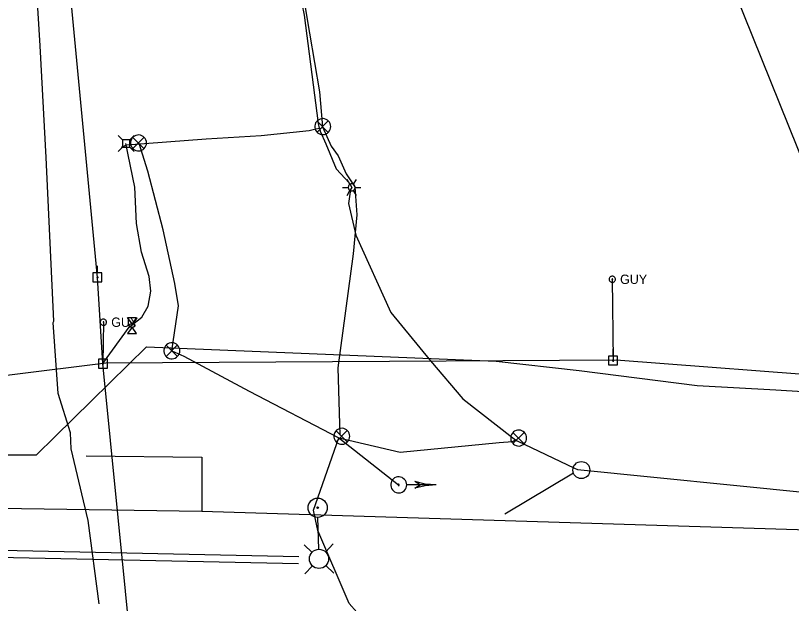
# Model space of a CAD drawing. Extents: x 596028 to 606371, y 330010 to 403088.
# Drawn here: x 603449.9 to 603769.8, y 349952.6 to 350195 of the extents above; entities that cross this region are included whole.
import ezdxf

# ---------------------------------------------------------------- set-up
doc = ezdxf.new("R2010")
doc.units = 0
for name, color, linetype in [('E_FTMS', 7, 'Continuous'), ('E_FTMS_Conduit', 7, 'Continuous'), ('E_LTG', 7, 'Continuous'), ('E_LTG_CID', 7, 'Continuous'), ('E_UTL_E', 7, 'Continuous'), ('E_UTL_E_Bold', 7, 'Continuous'), ('E_UTL_E_UG', 7, 'Continuous'), ('E_UTL_EGuyWire', 7, 'Continuous'), ('E_UTL_EPowerPole', 7, 'Continuous'), ('E_UTL_FO_UG_QWEST', 7, 'Continuous'), ('E_UTL_G_UG', 7, 'Continuous'), ('E_UTL_Overhead', 7, 'Continuous'), ('E_UTL_T_UG', 7, 'Continuous')]:
    doc.layers.add(name, color=color, linetype=linetype)

msp = doc.modelspace()

# ---------------------------------------------------------------- linework, layer by layer
at = {"layer": 'E_FTMS'}
msp.add_line((603679.91, 350006.37), (603651.7, 349989.5), dxfattribs=at)
for points in [[(603579.86, 350149.18), (603579.8, 350149.8), (603579.63, 350150.41), (603579.34, 350150.96), (603578.95, 350151.46), (603578.48, 350151.87), (603577.93, 350152.18), (603577.34, 350152.39), (603576.72, 350152.48), (603576.09, 350152.45), (603575.48, 350152.3), (603574.91, 350152.04), (603574.4, 350151.67), (603573.97, 350151.22), (603573.63, 350150.69), (603573.4, 350150.11), (603573.28, 350149.49), (603573.28, 350148.87), (603573.4, 350148.25), (603573.63, 350147.67), (603573.97, 350147.14), (603574.4, 350146.69), (603574.91, 350146.32), (603575.48, 350146.06), (603576.09, 350145.91), (603576.72, 350145.88), (603577.34, 350145.97), (603577.93, 350146.18), (603578.48, 350146.49), (603578.95, 350146.9), (603579.34, 350147.4), (603579.63, 350147.95), (603579.8, 350148.55), (603579.86, 350149.18)], [(603578.83, 350151.51), (603574.22, 350146.86)], [(603574.22, 350151.47), (603578.87, 350146.81)], [(603503.94, 350142.46), (603503.88, 350143.08), (603503.71, 350143.68), (603503.42, 350144.24), (603503.03, 350144.74), (603502.56, 350145.15), (603502.01, 350145.46), (603501.42, 350145.66), (603500.8, 350145.75), (603500.17, 350145.72), (603499.56, 350145.58), (603498.99, 350145.32), (603498.48, 350144.95), (603498.05, 350144.5), (603497.71, 350143.97), (603497.48, 350143.39), (603497.36, 350142.77), (603497.36, 350142.14), (603497.48, 350141.53), (603497.71, 350140.95), (603498.05, 350140.42), (603498.48, 350139.96), (603498.99, 350139.6), (603499.56, 350139.34), (603500.17, 350139.19), (603500.8, 350139.16), (603501.42, 350139.25), (603502.01, 350139.46), (603502.56, 350139.77), (603503.03, 350140.18), (603503.42, 350140.67), (603503.71, 350141.23), (603503.88, 350141.83), (603503.94, 350142.46)], [(603502.91, 350144.79), (603498.3, 350140.14)], [(603498.3, 350144.74), (603502.95, 350140.09)], [(603517.67, 350056.79), (603517.61, 350057.41), (603517.43, 350058.01), (603517.15, 350058.57), (603516.76, 350059.07), (603516.28, 350059.48), (603515.74, 350059.79), (603515.15, 350060), (603514.53, 350060.08), (603513.9, 350060.05), (603513.29, 350059.91), (603512.72, 350059.65), (603512.21, 350059.28), (603511.78, 350058.83), (603511.44, 350058.3), (603511.2, 350057.72), (603511.09, 350057.1), (603511.09, 350056.47), (603511.2, 350055.86), (603511.44, 350055.28), (603511.78, 350054.75), (603512.21, 350054.29), (603512.72, 350053.93), (603513.29, 350053.67), (603513.9, 350053.52), (603514.53, 350053.49), (603515.15, 350053.58), (603515.74, 350053.79), (603516.28, 350054.1), (603516.76, 350054.51), (603517.15, 350055), (603517.43, 350055.56), (603517.61, 350056.16), (603517.67, 350056.79)], [(603516.63, 350059.12), (603512.02, 350054.47)], [(603512.02, 350059.08), (603516.68, 350054.42)], [(603587.73, 350021.54), (603587.67, 350022.16), (603587.49, 350022.76), (603587.2, 350023.32), (603586.82, 350023.81), (603586.34, 350024.23), (603585.8, 350024.54), (603585.21, 350024.74), (603584.58, 350024.83), (603583.96, 350024.8), (603583.35, 350024.66), (603582.78, 350024.4), (603582.27, 350024.03), (603581.83, 350023.58), (603581.49, 350023.05), (603581.26, 350022.47), (603581.14, 350021.85), (603581.14, 350021.22), (603581.26, 350020.61), (603581.49, 350020.03), (603581.83, 350019.5), (603582.27, 350019.04), (603582.78, 350018.68), (603583.35, 350018.42), (603583.96, 350018.27), (603584.58, 350018.24), (603585.21, 350018.33), (603585.8, 350018.54), (603586.34, 350018.85), (603586.82, 350019.26), (603587.2, 350019.75), (603587.49, 350020.31), (603587.67, 350020.91), (603587.73, 350021.54)], [(603586.69, 350023.87), (603582.08, 350019.21)], [(603582.08, 350023.82), (603586.73, 350019.17)], [(603660.63, 350020.83), (603660.57, 350021.45), (603660.39, 350022.06), (603660.1, 350022.61), (603659.71, 350023.11), (603659.24, 350023.52), (603658.7, 350023.83), (603658.1, 350024.04), (603657.48, 350024.13), (603656.86, 350024.1), (603656.25, 350023.95), (603655.68, 350023.69), (603655.16, 350023.32), (603654.73, 350022.87), (603654.39, 350022.34), (603654.16, 350021.76), (603654.04, 350021.14), (603654.04, 350020.52), (603654.16, 350019.9), (603654.39, 350019.32), (603654.73, 350018.79), (603655.16, 350018.34), (603655.68, 350017.97), (603656.25, 350017.71), (603656.86, 350017.56), (603657.48, 350017.53), (603658.1, 350017.62), (603658.7, 350017.83), (603659.24, 350018.14), (603659.71, 350018.55), (603660.1, 350019.05), (603660.39, 350019.6), (603660.57, 350020.21), (603660.63, 350020.83)], [(603659.59, 350023.16), (603654.98, 350018.51)], [(603654.98, 350023.12), (603659.63, 350018.46)], [(603611.17, 350001.5), (603611.11, 350002.13), (603610.94, 350002.73), (603610.65, 350003.28), (603610.26, 350003.78), (603609.79, 350004.19), (603609.25, 350004.5), (603608.65, 350004.71), (603608.03, 350004.8), (603607.4, 350004.77), (603606.8, 350004.62), (603606.22, 350004.36), (603605.71, 350003.99), (603605.28, 350003.54), (603604.94, 350003.01), (603604.71, 350002.43), (603604.59, 350001.81), (603604.59, 350001.19), (603604.71, 350000.57), (603604.94, 349999.99), (603605.28, 349999.46), (603605.71, 349999.01), (603606.22, 349998.64), (603606.8, 349998.38), (603607.4, 349998.23), (603608.03, 349998.2), (603608.65, 349998.29), (603609.25, 349998.5), (603609.79, 349998.81), (603610.26, 349999.22), (603610.65, 349999.72), (603610.94, 350000.27), (603611.11, 350000.88), (603611.17, 350001.5)], [(603623.27, 350001.5), (603618.82, 350001.85), (603614.47, 350002.88)], [(603616.68, 350001.5), (603614.47, 350002.88)], [(603608.13, 350001.5), (603608.12, 350001.55), (603608.11, 350001.59), (603608.09, 350001.64), (603608.06, 350001.67), (603608.02, 350001.71), (603607.98, 350001.73), (603607.93, 350001.75), (603607.89, 350001.75), (603607.84, 350001.75), (603607.79, 350001.74), (603607.75, 350001.72), (603607.71, 350001.69), (603607.68, 350001.66), (603607.65, 350001.62), (603607.63, 350001.57), (603607.62, 350001.52), (603607.62, 350001.48), (603607.63, 350001.43), (603607.65, 350001.38), (603607.68, 350001.34), (603607.71, 350001.31), (603607.75, 350001.28), (603607.79, 350001.26), (603607.84, 350001.25), (603607.89, 350001.25), (603607.93, 350001.26), (603607.98, 350001.27), (603608.02, 350001.29), (603608.06, 350001.33), (603608.09, 350001.36), (603608.11, 350001.41), (603608.12, 350001.45), (603608.13, 350001.5)], [(603623.27, 350001.5), (603611.23, 350001.5)], [(603623.27, 350001.5), (603618.82, 350001.15), (603614.47, 350000.13)], [(603614.47, 350000.13), (603616.68, 350001.5)]]:
    msp.add_lwpolyline(points, dxfattribs=at)
msp.add_circle((603683.17, 350007.63), 3.5, dxfattribs=at)
at = {"layer": 'E_FTMS_Conduit'}
for points in [[(603776.07, 350130.97), (603746.49, 350204.79), (603740.19, 350221.54), (603705.21, 350305.05), (603700.59, 350327.76), (603696, 350362.93), (603683.28, 350388.39), (603627.38, 350513.3)], [(603565.86, 350218.8), (603571.07, 350187.75), (603575.18, 350163.49), (603576.5, 350149.08), (603580.05, 350141.16), (603582.94, 350137.08), (603586.21, 350129.73), (603589.8, 350124.4), (603590.67, 350112.8), (603589.13, 350096.71), (603582.8, 350049.8), (603583.68, 350022)], [(603493.66, 350140.75), (603495.84, 350141.7), (603528.48, 350144.11), (603551.14, 350145.54), (603570.99, 350147.6), (603573.77, 350148.28), (603575.19, 350148.59)], [(603514.37, 350056.79), (603517.13, 350075.28), (603515.66, 350084.52), (603510.83, 350106.62), (603504.46, 350130.87), (603500.87, 350142.28)], [(603514.37, 350056.79), (603519.33, 350054.54), (603546.19, 350040.11), (603583.24, 350020.86)], [(603583.24, 350020.86), (603607.87, 350001.5)], [(603583.24, 350020.86), (603608.49, 350015.05), (603649.23, 350018.98), (603654.78, 350019.38), (603655.98, 350020.11), (603656.75, 350019.7), (603680.35, 350008.39), (603681.64, 350007.87)]]:
    msp.add_lwpolyline(points, dxfattribs=at)
at = {"layer": 'E_LTG'}
for points in [[(603587.8, 350125.4), (603586.6, 350127.46)], [(603589.22, 350125.4), (603590.42, 350127.46)], [(603584.7, 350124.16), (603587.08, 350124.16)], [(603589.94, 350124.16), (603589.91, 350124.43), (603589.84, 350124.69), (603589.71, 350124.93), (603589.54, 350125.15), (603589.34, 350125.32), (603589.1, 350125.46), (603588.85, 350125.55), (603588.58, 350125.59), (603588.31, 350125.57), (603588.04, 350125.51), (603587.8, 350125.4), (603587.57, 350125.24), (603587.39, 350125.04), (603587.24, 350124.81), (603587.14, 350124.56), (603587.09, 350124.3), (603587.09, 350124.02), (603587.14, 350123.76), (603587.24, 350123.5), (603587.39, 350123.28), (603587.57, 350123.08), (603587.8, 350122.92), (603588.04, 350122.81), (603588.31, 350122.75), (603588.58, 350122.73), (603588.85, 350122.77), (603589.1, 350122.86), (603589.34, 350123), (603589.54, 350123.17), (603589.71, 350123.39), (603589.84, 350123.63), (603589.91, 350123.89), (603589.94, 350124.16)], [(603589.94, 350124.16), (603589.91, 350124.43), (603589.84, 350124.69), (603589.71, 350124.93), (603589.54, 350125.15), (603589.34, 350125.32), (603589.1, 350125.46), (603588.85, 350125.55), (603588.58, 350125.59), (603588.31, 350125.57), (603588.04, 350125.51), (603587.8, 350125.4), (603587.57, 350125.24), (603587.39, 350125.04), (603587.24, 350124.81), (603587.14, 350124.56), (603587.09, 350124.3), (603587.09, 350124.02), (603587.14, 350123.76), (603587.24, 350123.5), (603587.39, 350123.28), (603587.57, 350123.08), (603587.8, 350122.92), (603588.04, 350122.81), (603588.31, 350122.75), (603588.58, 350122.73), (603588.85, 350122.77), (603589.1, 350122.86), (603589.34, 350123), (603589.54, 350123.17), (603589.71, 350123.39), (603589.84, 350123.63), (603589.91, 350123.89), (603589.94, 350124.16)], [(603589.94, 350124.16), (603589.91, 350124.43), (603589.84, 350124.69), (603589.71, 350124.93), (603589.54, 350125.15), (603589.34, 350125.32), (603589.1, 350125.46), (603588.85, 350125.55), (603588.58, 350125.59), (603588.31, 350125.57), (603588.04, 350125.51), (603587.8, 350125.4), (603587.57, 350125.24), (603587.39, 350125.04), (603587.24, 350124.81), (603587.14, 350124.56), (603587.09, 350124.3), (603587.09, 350124.02), (603587.14, 350123.76), (603587.24, 350123.5), (603587.39, 350123.28), (603587.57, 350123.08), (603587.8, 350122.92), (603588.04, 350122.81), (603588.31, 350122.75), (603588.58, 350122.73), (603588.85, 350122.77), (603589.1, 350122.86), (603589.34, 350123), (603589.54, 350123.17), (603589.71, 350123.39), (603589.84, 350123.63), (603589.91, 350123.89), (603589.94, 350124.16)], [(603588.63, 350124.16), (603588.63, 350124.18), (603588.62, 350124.2), (603588.61, 350124.22), (603588.6, 350124.24), (603588.58, 350124.26), (603588.56, 350124.27), (603588.54, 350124.28), (603588.52, 350124.28), (603588.49, 350124.28), (603588.47, 350124.27), (603588.45, 350124.26), (603588.43, 350124.25), (603588.42, 350124.23), (603588.4, 350124.21), (603588.4, 350124.19), (603588.39, 350124.17), (603588.39, 350124.15), (603588.4, 350124.13), (603588.4, 350124.11), (603588.42, 350124.09), (603588.43, 350124.07), (603588.45, 350124.06), (603588.47, 350124.05), (603588.49, 350124.04), (603588.52, 350124.04), (603588.54, 350124.04), (603588.56, 350124.05), (603588.58, 350124.06), (603588.6, 350124.08), (603588.61, 350124.1), (603588.62, 350124.12), (603588.63, 350124.14), (603588.63, 350124.16)], [(603589.94, 350124.16), (603592.32, 350124.16)], [(603586.6, 350120.86), (603587.8, 350122.92)], [(603590.42, 350120.86), (603589.22, 350122.92)], [(603574.91, 349975.02), (603574.57, 349988.06)], [(603572.18, 349973.69), (603568.87, 349976.84)], [(603577.72, 349973.83), (603580.86, 349977.15)], [(603572.33, 349968.15), (603569.18, 349964.84)], [(603577.86, 349968.3), (603581.17, 349965.15)]]:
    msp.add_lwpolyline(points, dxfattribs=at)
for centre, radius in [((603574.47, 349992.09), 3.96), ((603574.47, 349992.09), 0.303), ((603575.02, 349971), 3.96)]:
    msp.add_circle(centre, radius, dxfattribs=at)
at = {"layer": 'E_LTG_CID'}
msp.add_line((603681.64, 350007.87), (603786.08, 349997.29), dxfattribs=at)
for points in [[(603575.2, 350148.58), (603574.89, 350150.51), (603569.1, 350195.08), (603562.31, 350228.01), (603558.55, 350246.32), (603558.29, 350247.63), (603558.39, 350249.04), (603556.28, 350264.17), (603551.3, 350293.34), (603549.66, 350312.26), (603546.66, 350330.89), (603540.76, 350362.51), (603535.43, 350396.52), (603532.14, 350428.2), (603538.88, 350433.66), (603549.37, 350446.22)], [(603575.2, 350148.58), (603575.49, 350147.29), (603577.82, 350142.15), (603582.07, 350131.77), (603587.61, 350125.84), (603588.51, 350124.16), (603587.98, 350123.3), (603587.16, 350117.48), (603590.23, 350104.45), (603604.63, 350072.51), (603620.98, 350052.63), (603634.38, 350037.03), (603654.88, 350020.9), (603655.98, 350020.11)], [(603572.73, 349991.09), (603583.24, 350020.86)], [(603621.26, 349910.44), (603620.8, 349911.86), (603616.21, 349917.99), (603593.76, 349945.42), (603587.47, 349952.66), (603574.53, 349982.77), (603572.73, 349991.09)]]:
    msp.add_lwpolyline(points, dxfattribs=at)
at = {"layer": 'E_UTL_E'}
for points in [[(603493.97, 350143.75), (603492.21, 350145.5)], [(603497.06, 350143.75), (603493.97, 350143.75)], [(603493.97, 350143.75), (603493.97, 350140.66)], [(603497.06, 350143.75), (603498.81, 350145.5)], [(603497.06, 350140.66), (603497.06, 350143.75)], [(603493.97, 350140.66), (603492.21, 350138.9)], [(603493.97, 350140.66), (603497.06, 350140.66)], [(603497.06, 350140.66), (603498.81, 350138.9)]]:
    msp.add_lwpolyline(points, dxfattribs=at)
at = {"layer": 'E_UTL_E_Bold'}
for points in [[(603496.05, 350070.49), (603499.86, 350070.49)], [(603497.95, 350067.83), (603496.05, 350070.49)], [(603499.86, 350070.49), (603497.95, 350067.83)], [(603497.95, 350066.56), (603496.05, 350063.89)], [(603499.22, 350067.19), (603499.2, 350067.31), (603499.13, 350067.43), (603499.02, 350067.54), (603498.87, 350067.63), (603498.69, 350067.71), (603498.48, 350067.77), (603498.25, 350067.81), (603498.01, 350067.83), (603497.77, 350067.82), (603497.54, 350067.79), (603497.32, 350067.74), (603497.12, 350067.67), (603496.96, 350067.58), (603496.82, 350067.48), (603496.74, 350067.37), (603496.69, 350067.25), (603496.69, 350067.13), (603496.74, 350067.01), (603496.82, 350066.9), (603496.96, 350066.8), (603497.12, 350066.71), (603497.32, 350066.64), (603497.54, 350066.59), (603497.77, 350066.56), (603498.01, 350066.56), (603498.25, 350066.57), (603498.48, 350066.61), (603498.69, 350066.67), (603498.87, 350066.75), (603499.02, 350066.85), (603499.13, 350066.96), (603499.2, 350067.07), (603499.22, 350067.19)], [(603499.86, 350063.89), (603497.95, 350066.56)], [(603496.05, 350063.89), (603499.86, 350063.89)]]:
    msp.add_lwpolyline(points, dxfattribs=at)
at = {"layer": 'E_UTL_E_UG'}
msp.add_lwpolyline([(603485.97, 350051.51), (603496.71, 350066.56), (603497.45, 350067.05), (603502.05, 350070.65), (603504.61, 350075.23), (603505.7, 350081.37), (603504.98, 350087.44), (603501.88, 350097.49), (603499.75, 350109.27), (603499.11, 350124.26), (603495.41, 350142.26)], dxfattribs=at)
at = {"layer": 'E_UTL_EGuyWire'}
for p, q in [((603695.93, 350086.25), (603696.28, 350052.77)), ((603486.17, 350068.57), (603485.97, 350051.51))]:
    msp.add_line(p, q, dxfattribs=at)
for points in [[(603697.21, 350086.25), (603697.19, 350086.49), (603697.12, 350086.73), (603697.01, 350086.94), (603696.86, 350087.14), (603696.67, 350087.3), (603696.46, 350087.42), (603696.23, 350087.5), (603695.99, 350087.53), (603695.75, 350087.52), (603695.51, 350087.46), (603695.29, 350087.36), (603695.09, 350087.22), (603694.92, 350087.04), (603694.79, 350086.84), (603694.7, 350086.61), (603694.65, 350086.37), (603694.65, 350086.13), (603694.7, 350085.89), (603694.79, 350085.66), (603694.92, 350085.46), (603695.09, 350085.28), (603695.29, 350085.14), (603695.51, 350085.04), (603695.75, 350084.98), (603695.99, 350084.97), (603696.23, 350085), (603696.46, 350085.08), (603696.67, 350085.2), (603696.86, 350085.36), (603697.01, 350085.56), (603697.12, 350085.77), (603697.19, 350086.01), (603697.21, 350086.25)], [(603696.09, 350086.25), (603696.09, 350086.28), (603696.08, 350086.31), (603696.06, 350086.34), (603696.05, 350086.36), (603696.02, 350086.38), (603696, 350086.4), (603695.97, 350086.41), (603695.94, 350086.41), (603695.91, 350086.41), (603695.88, 350086.4), (603695.85, 350086.39), (603695.82, 350086.37), (603695.8, 350086.35), (603695.79, 350086.32), (603695.78, 350086.3), (603695.77, 350086.27), (603695.77, 350086.23), (603695.78, 350086.2), (603695.79, 350086.18), (603695.8, 350086.15), (603695.82, 350086.13), (603695.85, 350086.11), (603695.88, 350086.1), (603695.91, 350086.09), (603695.94, 350086.09), (603695.97, 350086.09), (603696, 350086.1), (603696.02, 350086.12), (603696.05, 350086.14), (603696.06, 350086.16), (603696.08, 350086.19), (603696.09, 350086.22), (603696.09, 350086.25)], [(603487.45, 350068.57), (603487.43, 350068.81), (603487.36, 350069.04), (603487.25, 350069.26), (603487.1, 350069.45), (603486.91, 350069.61), (603486.7, 350069.73), (603486.47, 350069.81), (603486.23, 350069.85), (603485.99, 350069.84), (603485.75, 350069.78), (603485.53, 350069.68), (603485.33, 350069.54), (603485.16, 350069.36), (603485.03, 350069.15), (603484.94, 350068.93), (603484.89, 350068.69), (603484.89, 350068.44), (603484.94, 350068.2), (603485.03, 350067.98), (603485.16, 350067.77), (603485.33, 350067.6), (603485.53, 350067.45), (603485.75, 350067.35), (603485.99, 350067.3), (603486.23, 350067.28), (603486.47, 350067.32), (603486.7, 350067.4), (603486.91, 350067.52), (603487.1, 350067.68), (603487.25, 350067.87), (603487.36, 350068.09), (603487.43, 350068.32), (603487.45, 350068.57)], [(603486.33, 350068.57), (603486.33, 350068.6), (603486.32, 350068.63), (603486.3, 350068.65), (603486.29, 350068.68), (603486.26, 350068.7), (603486.24, 350068.71), (603486.21, 350068.72), (603486.18, 350068.73), (603486.15, 350068.72), (603486.12, 350068.72), (603486.09, 350068.7), (603486.06, 350068.69), (603486.04, 350068.67), (603486.03, 350068.64), (603486.02, 350068.61), (603486.01, 350068.58), (603486.01, 350068.55), (603486.02, 350068.52), (603486.03, 350068.49), (603486.04, 350068.47), (603486.06, 350068.44), (603486.09, 350068.43), (603486.12, 350068.41), (603486.15, 350068.41), (603486.18, 350068.41), (603486.21, 350068.41), (603486.24, 350068.42), (603486.26, 350068.44), (603486.29, 350068.46), (603486.3, 350068.48), (603486.32, 350068.51), (603486.33, 350068.54), (603486.33, 350068.57)]]:
    msp.add_lwpolyline(points, dxfattribs=at)
at = {"layer": 'E_UTL_EPowerPole'}
for points in [[(603483.7, 350088.89), (603483.7, 350091.8)], [(603485.54, 350088.89), (603481.86, 350088.89)], [(603481.86, 350088.89), (603481.86, 350085.2)], [(603485.54, 350085.2), (603485.54, 350088.89)], [(603483.97, 350087.05), (603483.97, 350087.09), (603483.95, 350087.14), (603483.93, 350087.18), (603483.9, 350087.21), (603483.87, 350087.24), (603483.83, 350087.27), (603483.79, 350087.28), (603483.74, 350087.29), (603483.7, 350087.29), (603483.65, 350087.27), (603483.61, 350087.26), (603483.58, 350087.23), (603483.54, 350087.2), (603483.52, 350087.16), (603483.5, 350087.12), (603483.49, 350087.07), (603483.49, 350087.03), (603483.5, 350086.98), (603483.52, 350086.94), (603483.54, 350086.9), (603483.58, 350086.87), (603483.61, 350086.84), (603483.65, 350086.82), (603483.7, 350086.81), (603483.74, 350086.81), (603483.79, 350086.82), (603483.83, 350086.83), (603483.87, 350086.85), (603483.9, 350086.88), (603483.93, 350086.92), (603483.95, 350086.96), (603483.97, 350087), (603483.97, 350087.05)], [(603481.86, 350085.2), (603485.54, 350085.2)], [(603696.24, 350054.62), (603696.24, 350057.53)], [(603487.78, 350053.35), (603484.09, 350053.35)], [(603484.09, 350053.35), (603484.09, 350049.66)], [(603485.94, 350053.35), (603485.94, 350056.26)], [(603487.78, 350049.66), (603487.78, 350053.35)], [(603698.09, 350054.62), (603694.4, 350054.62)], [(603694.4, 350054.62), (603694.4, 350050.93)], [(603698.09, 350050.93), (603698.09, 350054.62)], [(603486.21, 350051.51), (603486.2, 350051.56), (603486.19, 350051.6), (603486.17, 350051.64), (603486.14, 350051.68), (603486.11, 350051.71), (603486.07, 350051.73), (603486.03, 350051.74), (603485.98, 350051.75), (603485.94, 350051.75), (603485.89, 350051.74), (603485.85, 350051.72), (603485.81, 350051.69), (603485.78, 350051.66), (603485.76, 350051.62), (603485.74, 350051.58), (603485.73, 350051.53), (603485.73, 350051.49), (603485.74, 350051.44), (603485.76, 350051.4), (603485.78, 350051.36), (603485.81, 350051.33), (603485.85, 350051.31), (603485.89, 350051.29), (603485.94, 350051.28), (603485.98, 350051.27), (603486.03, 350051.28), (603486.07, 350051.3), (603486.11, 350051.32), (603486.14, 350051.35), (603486.17, 350051.38), (603486.19, 350051.42), (603486.2, 350051.47), (603486.21, 350051.51)], [(603694.4, 350050.93), (603698.09, 350050.93)], [(603696.52, 350052.77), (603696.51, 350052.82), (603696.5, 350052.86), (603696.48, 350052.9), (603696.45, 350052.94), (603696.42, 350052.97), (603696.38, 350052.99), (603696.33, 350053.01), (603696.29, 350053.01), (603696.24, 350053.01), (603696.2, 350053), (603696.16, 350052.98), (603696.12, 350052.95), (603696.09, 350052.92), (603696.06, 350052.88), (603696.05, 350052.84), (603696.04, 350052.8), (603696.04, 350052.75), (603696.05, 350052.71), (603696.06, 350052.66), (603696.09, 350052.63), (603696.12, 350052.59), (603696.16, 350052.57), (603696.2, 350052.55), (603696.24, 350052.54), (603696.29, 350052.54), (603696.33, 350052.54), (603696.38, 350052.56), (603696.42, 350052.58), (603696.45, 350052.61), (603696.48, 350052.65), (603696.5, 350052.69), (603696.51, 350052.73), (603696.52, 350052.77)], [(603484.09, 350049.66), (603487.78, 350049.66)]]:
    msp.add_lwpolyline(points, dxfattribs=at)
at = {"layer": 'E_UTL_FO_UG_QWEST'}
msp.add_lwpolyline([(603484.43, 349952.42), (603479.94, 349986.84), (603472.93, 350016.37), (603472.53, 350022.97), (603467.48, 350039.11), (603465.43, 350068.42), (603465.78, 350068.99), (603462.63, 350136.46), (603460.06, 350182.47), (603456.92, 350234.22), (603462.57, 350276.57), (603464.06, 350325.25), (603464.23, 350373.72), (603456.32, 350421.92), (603453.14, 350468.35)], dxfattribs=at)
at = {"layer": 'E_UTL_G_UG'}
for points in [[(603247.07, 350019.95), (603318.24, 350017.66), (603336.79, 350016.35), (603384.58, 350014.07), (603430.96, 350013.96), (603458.52, 350013.84), (603503.86, 350058.46), (603648.07, 350052.57), (603682.34, 350048.59), (603730.88, 350042.54), (603763.3, 350040.62), (603792.31, 350038.87), (603814.03, 350037.15), (603835.65, 350036.86), (603952.18, 350026.33), (603985.15, 350025.13), (604017.27, 350023.85), (604050.12, 350022.04), (604102.3, 350017.06), (604148.94, 350012.3), (604207.72, 350003.02), (604224.15, 350001.18), (604252.85, 349997.07), (604335.69, 349990.44)], [(603479.05, 350013.55), (603526.72, 350012.88), (603526.72, 349990.73)], [(602826.9, 349977.26), (603315.02, 349970.71), (603331.6, 349993.52), (603526.72, 349990.73), (604482.07, 349961.23)]]:
    msp.add_lwpolyline(points, dxfattribs=at)
at = {"layer": 'E_UTL_Overhead'}
msp.add_line((603483.73, 350087.05), (603468.46, 350246.59), dxfattribs=at)
for points in [[(603501.53, 349894.25), (603485.97, 350051.51), (603483.73, 350087.05)], [(603181.28, 350035.1), (603329.32, 350032.13), (603487.19, 350051.84), (603697.5, 350053.11), (603794.73, 350045.64), (603986.8, 350030.72), (604135.55, 350019.1), (604355.8, 350001.36), (604456.04, 349993.24), (604557.11, 349986.14), (604654.49, 349982.64), (604747.33, 349981.14), (604855.96, 349980.06), (604969.76, 349979.4), (605156.33, 349975.18)]]:
    msp.add_lwpolyline(points, dxfattribs=at)
at = {"layer": 'E_UTL_T_UG'}
msp.add_line((602560.12, 349990.4), (603566.6, 349969.05), dxfattribs=at)
msp.add_lwpolyline([(602560.18, 349993.4), (603566.67, 349972.04)], dxfattribs=at)

# ---------------------------------------------------------------- texts
at = {"layer": 'E_UTL_EGuyWire'}
for p in [(603699.14, 350084.33), (603489.38, 350066.64)]:
    msp.add_text('GUY', height=3.85, dxfattribs=at).set_placement(p)

doc.saveas('drawing.dxf')
